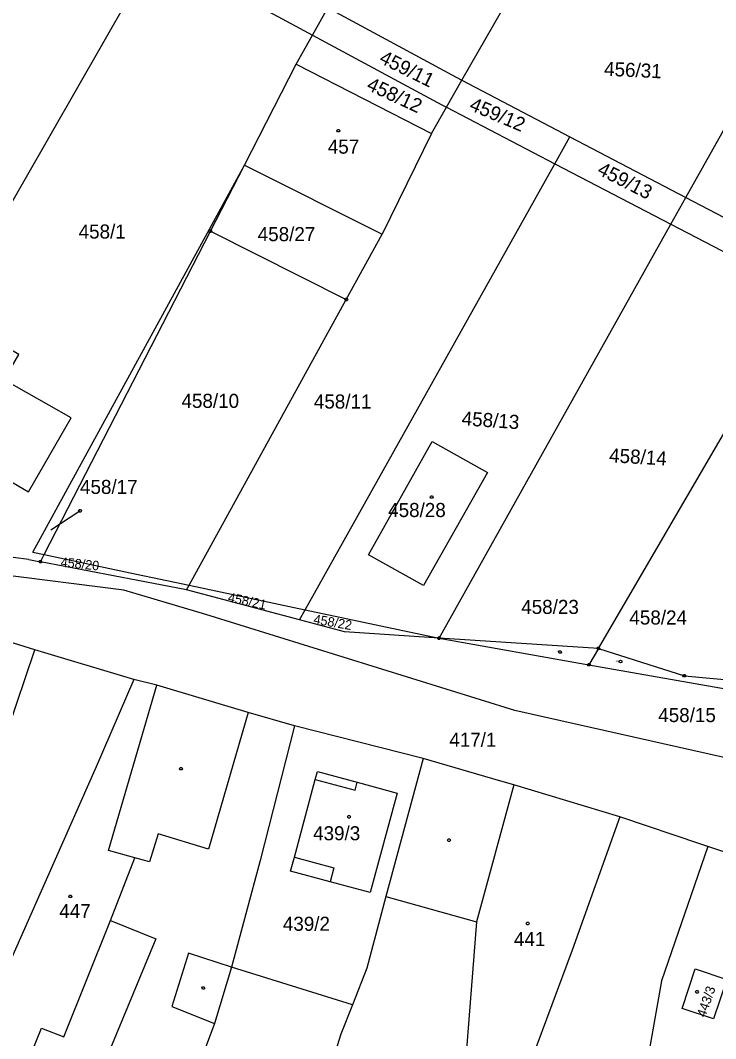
# Model space of a CAD drawing. Extents: x -634640 to -629202, y -1196156 to -1190068.
# Drawn here: x -631677.2 to -631593.2, y -1192457.5 to -1192334.4 of the extents above; entities that cross this region are included whole.
import ezdxf

# ---------------------------------------------------------------- set-up
doc = ezdxf.new("R2010")
doc.units = 0
for name, color, linetype in [('Vrstva 1', 7, 'Continuous'), ('Vrstva 2', 7, 'Continuous'), ('Vrstva 3', 7, 'Continuous'), ('Vrstva 4', 7, 'Continuous'), ('Vrstva 5', 7, 'Continuous'), ('Vrstva 7', 7, 'Continuous'), ('Vrstva 8', 7, 'Continuous')]:
    doc.layers.add(name, color=color, linetype=linetype)

msp = doc.modelspace()

# ---------------------------------------------------------------- linework, layer by layer
at = {"layer": 'Vrstva 1'}
for p, q in [((-631596.84, -1192355.81), (-631551.04, -1192273.99)), ((-631623.88, -1192341.65), (-631611.53, -1192319.92)), ((-631699.56, -1192393.62), (-631660.85, -1192325.98)), ((-631660.85, -1192325.98), (-631641.92, -1192336.19)), ((-631641.92, -1192336.19), (-631640.07, -1192332.88)), ((-631640.07, -1192332.88), (-631624.58, -1192341.28)), ((-631643.89, -1192339.71), (-631641.92, -1192336.19)), ((-631641.92, -1192336.19), (-631626.3, -1192344.61)), ((-631650.15, -1192351.9), (-631643.89, -1192339.71)), ((-631643.89, -1192339.71), (-631627.54, -1192348.09)), ((-631625.73, -1192344.91), (-631623.88, -1192341.65)), ((-631624.58, -1192341.28), (-631623.88, -1192341.65)), ((-631623.88, -1192341.65), (-631610.84, -1192348.48)), ((-631626.3, -1192344.61), (-631625.73, -1192344.91)), ((-631627.54, -1192348.09), (-631625.73, -1192344.91)), ((-631625.73, -1192344.91), (-631612.65, -1192351.73)), ((-631627.54, -1192348.09), (-631633.52, -1192360.26)), ((-631612.65, -1192351.73), (-631610.84, -1192348.48)), ((-631610.84, -1192348.48), (-631596.84, -1192355.81)), ((-631675.69, -1192398.68), (-631650.15, -1192351.9)), ((-631654.26, -1192359.89), (-631650.15, -1192351.9)), ((-631650.15, -1192351.9), (-631633.52, -1192360.26)), ((-631642.81, -1192405.64), (-631612.65, -1192351.73)), ((-631612.65, -1192351.73), (-631598.65, -1192359.03)), ((-631598.65, -1192359.03), (-631596.84, -1192355.81)), ((-631596.84, -1192355.81), (-631580.61, -1192364.32)), ((-631626.65, -1192409.06), (-631598.65, -1192359.03)), ((-631598.65, -1192359.03), (-631582.45, -1192367.48)), ((-631674.34, -1192398.96), (-631654.26, -1192359.89)), ((-631654.26, -1192359.89), (-631637.85, -1192368.14)), ((-631637.85, -1192368.14), (-631633.52, -1192360.26)), ((-631607.4, -1192410.3), (-631582.45, -1192367.48)), ((-631656.83, -1192402.67), (-631637.85, -1192368.14)), ((-631635.17, -1192398.98), (-631627.48, -1192385.29)), ((-631627.48, -1192385.29), (-631620.81, -1192389.06)), ((-631620.81, -1192389.06), (-631628.54, -1192402.72)), ((-631676.17, -1192399.56), (-631701.21, -1192396.5)), ((-631675.69, -1192398.68), (-631674.34, -1192398.96)), ((-631676.17, -1192399.56), (-631674.79, -1192399.83)), ((-631674.79, -1192399.83), (-631674.34, -1192398.96)), ((-631657.14, -1192403.23), (-631674.79, -1192399.83)), ((-631674.34, -1192398.96), (-631663.96, -1192401.16)), ((-631628.54, -1192402.72), (-631635.17, -1192398.98)), ((-631664.73, -1192403.25), (-631685.49, -1192400.66)), ((-631663.96, -1192401.16), (-631656.83, -1192402.67)), ((-631654.83, -1192406.19), (-631664.73, -1192403.25)), ((-631657.14, -1192403.23), (-631656.83, -1192402.67)), ((-631643.5, -1192406.87), (-631657.14, -1192403.23)), ((-631656.83, -1192402.67), (-631642.81, -1192405.64)), ((-631643.5, -1192406.87), (-631642.81, -1192405.64)), ((-631642.81, -1192405.64), (-631626.65, -1192409.06)), ((-631617.48, -1192417.8), (-631654.83, -1192406.19)), ((-631638.06, -1192408.32), (-631643.5, -1192406.87)), ((-631626.65, -1192409.06), (-631638.06, -1192408.32)), ((-631675.46, -1192410.46), (-631680.01, -1192409.08)), ((-631607.4, -1192410.3), (-631626.65, -1192409.06)), ((-631626.65, -1192409.06), (-631608.55, -1192412.27)), ((-631663.51, -1192414.07), (-631675.46, -1192410.46)), ((-631607.4, -1192410.3), (-631608.55, -1192412.27)), ((-631607.4, -1192410.3), (-631597.02, -1192413.6)), ((-631608.55, -1192412.27), (-631587.87, -1192415.94)), ((-631663.51, -1192414.07), (-631668.06, -1192424.6)), ((-631666.57, -1192434.71), (-631660.73, -1192414.76)), ((-631660.73, -1192414.76), (-631663.51, -1192414.07)), ((-631649.72, -1192418.05), (-631660.73, -1192414.76)), ((-631597.02, -1192413.6), (-631587.02, -1192414.54)), ((-631644.12, -1192419.68), (-631649.72, -1192418.05)), ((-631573.53, -1192427.73), (-631617.48, -1192417.8)), ((-631644.12, -1192419.68), (-631648.26, -1192435.93)), ((-631628.57, -1192423.59), (-631644.12, -1192419.68)), ((-631668.06, -1192424.6), (-631683.05, -1192458.47)), ((-631628.57, -1192423.59), (-631633.08, -1192440.27)), ((-631619.17, -1192426.33), (-631628.57, -1192423.59)), ((-631641.59, -1192426.15), (-631641.33, -1192425.18)), ((-631641.33, -1192425.18), (-631636.52, -1192426.47)), ((-631644.12, -1192435.54), (-631641.59, -1192426.15)), ((-631617.63, -1192426.79), (-631622.14, -1192443.33)), ((-631617.63, -1192426.79), (-631619.17, -1192426.33)), ((-631604.81, -1192430.67), (-631617.63, -1192426.79)), ((-631604.81, -1192430.67), (-631610.57, -1192446.78)), ((-631595.05, -1192433.96), (-631604.81, -1192430.67)), ((-631594.19, -1192434.24), (-631599.8, -1192450.48)), ((-631594.19, -1192434.24), (-631595.05, -1192433.96)), ((-631581.89, -1192438.36), (-631594.19, -1192434.24)), ((-631663.38, -1192435.6), (-631666.57, -1192434.71)), ((-631666.32, -1192443.2), (-631663.38, -1192435.6)), ((-631648.26, -1192435.93), (-631651.72, -1192448.81)), ((-631633.08, -1192440.27), (-631635.36, -1192448.94)), ((-631671.98, -1192457.26), (-631666.32, -1192443.2)), ((-631622.14, -1192443.33), (-631623.36, -1192459.26)), ((-631610.57, -1192446.78), (-631615.48, -1192459.99)), ((-631651.72, -1192448.81), (-631653.75, -1192455.62)), ((-631637.11, -1192453.38), (-631651.72, -1192448.81)), ((-631635.36, -1192448.94), (-631637.11, -1192453.38)), ((-631599.8, -1192450.48), (-631602.23, -1192464.48)), ((-631637.11, -1192453.38), (-631638.51, -1192456.92)), ((-631676.93, -1192461.8), (-631674.65, -1192456.19)), ((-631674.65, -1192456.19), (-631671.98, -1192457.26)), ((-631653.75, -1192455.62), (-631659.87, -1192471.73)), ((-631638.51, -1192456.92), (-631643.13, -1192471.72))]:
    msp.add_line(p, q, dxfattribs=at)
for points in [[(-631690.67, -1192385.37), (-631686.42, -1192387.83), (-631684.38, -1192386.65), (-631676.21, -1192391.4), (-631671.07, -1192382.44), (-631679.16, -1192377.83), (-631677.41, -1192374.77), (-631682.85, -1192371.59), (-631690.67, -1192385.37)], [(-631682.88, -1192418.91), (-631678.82, -1192420.38), (-631675.46, -1192410.46)], [(-631636.52, -1192426.47), (-631631.71, -1192427.8), (-631634.96, -1192439.8), (-631639.79, -1192438.5)], [(-631639.79, -1192438.5), (-631644.57, -1192437.22), (-631644.12, -1192435.54)], [(-631597.29, -1192453.81), (-631595.7, -1192449.03), (-631591.88, -1192450.3), (-631593.51, -1192455.07), (-631597.29, -1192453.81)]]:
    msp.add_lwpolyline(points, dxfattribs=at)
at = {"layer": 'Vrstva 3'}
for points in [[(-631671.09, -1192440.12), (-631671, -1192440.27), (-631671.09, -1192440.42), (-631671.27, -1192440.42), (-631671.36, -1192440.27), (-631671.27, -1192440.12), (-631671.09, -1192440.12)], [(-631615.85, -1192443.39), (-631615.76, -1192443.54), (-631615.85, -1192443.69), (-631616.03, -1192443.69), (-631616.12, -1192443.54), (-631616.03, -1192443.39), (-631615.85, -1192443.39)]]:
    msp.add_lwpolyline(points, dxfattribs=at)
at = {"layer": 'Vrstva 4'}
for p, q in [((-631649.72, -1192418.05), (-631654.5, -1192434.56)), ((-631660.57, -1192432.7), (-631661.61, -1192436.09)), ((-631654.5, -1192434.56), (-631660.57, -1192432.7)), ((-631661.61, -1192436.09), (-631663.38, -1192435.6)), ((-631633.08, -1192440.27), (-631622.14, -1192443.33)), ((-631666.32, -1192443.2), (-631660.86, -1192445.4)), ((-631660.86, -1192445.4), (-631668.2, -1192463.07)), ((-631656.9, -1192447.12), (-631658.9, -1192453.56)), ((-631651.72, -1192448.81), (-631656.9, -1192447.12)), ((-631658.9, -1192453.56), (-631653.75, -1192455.62))]:
    msp.add_line(p, q, dxfattribs=at)
for points in [[(-631641.59, -1192426.15), (-631636.78, -1192427.44), (-631636.52, -1192426.47)], [(-631644.12, -1192435.54), (-631639.34, -1192436.82), (-631639.79, -1192438.5)]]:
    msp.add_lwpolyline(points, dxfattribs=at)
at = {"layer": 'Vrstva 5'}
for points in [[(-631638.72, -1192347.6), (-631638.63, -1192347.75), (-631638.72, -1192347.9), (-631638.9, -1192347.9), (-631638.99, -1192347.75), (-631638.9, -1192347.6), (-631638.72, -1192347.6)], [(-631627.44, -1192391.86), (-631627.35, -1192392.01), (-631627.44, -1192392.16), (-631627.62, -1192392.16), (-631627.71, -1192392.01), (-631627.62, -1192391.86), (-631627.44, -1192391.86)], [(-631657.73, -1192424.69), (-631657.64, -1192424.84), (-631657.73, -1192424.99), (-631657.91, -1192424.99), (-631658, -1192424.84), (-631657.91, -1192424.69), (-631657.73, -1192424.69)], [(-631637.43, -1192430.5), (-631637.34, -1192430.65), (-631637.43, -1192430.8), (-631637.61, -1192430.8), (-631637.7, -1192430.65), (-631637.61, -1192430.5), (-631637.43, -1192430.5)], [(-631625.35, -1192433.33), (-631625.26, -1192433.48), (-631625.35, -1192433.63), (-631625.53, -1192433.63), (-631625.62, -1192433.48), (-631625.53, -1192433.33), (-631625.35, -1192433.33)], [(-631655.04, -1192451.19), (-631654.95, -1192451.34), (-631655.04, -1192451.49), (-631655.22, -1192451.49), (-631655.31, -1192451.34), (-631655.22, -1192451.19), (-631655.04, -1192451.19)], [(-631595.42, -1192451.66), (-631595.33, -1192451.81), (-631595.42, -1192451.96), (-631595.6, -1192451.96), (-631595.69, -1192451.81), (-631595.6, -1192451.66), (-631595.42, -1192451.66)]]:
    msp.add_lwpolyline(points, dxfattribs=at)
at = {"layer": 'Vrstva 7'}
msp.add_line((-631673.54, -1192395.97), (-631670.02, -1192393.68), dxfattribs=at)
for points in [[(-631669.845, -1192393.674), (-631669.922, -1192393.831), (-631670.097, -1192393.837), (-631670.195, -1192393.686), (-631670.118, -1192393.529), (-631669.943, -1192393.523), (-631669.845, -1192393.674)], [(-631611.944, -1192410.594), (-631611.86, -1192410.747), (-631611.956, -1192410.893), (-631612.136, -1192410.886), (-631612.22, -1192410.733), (-631612.124, -1192410.587), (-631611.944, -1192410.594)], [(-631604.571, -1192411.818), (-631604.582, -1192411.992), (-631604.741, -1192412.065), (-631604.889, -1192411.962), (-631604.878, -1192411.788), (-631604.719, -1192411.715), (-631604.571, -1192411.818)]]:
    msp.add_lwpolyline(points, dxfattribs=at)
at = {"layer": 'Vrstva 8'}
for points in [[(-631654.17, -1192359.74), (-631654.08, -1192359.89), (-631654.17, -1192360.04), (-631654.35, -1192360.04), (-631654.44, -1192359.89), (-631654.35, -1192359.74), (-631654.17, -1192359.74)], [(-631637.76, -1192367.99), (-631637.67, -1192368.14), (-631637.76, -1192368.29), (-631637.94, -1192368.29), (-631638.03, -1192368.14), (-631637.94, -1192367.99), (-631637.76, -1192367.99)], [(-631674.7, -1192399.68), (-631674.61, -1192399.83), (-631674.7, -1192399.98), (-631674.88, -1192399.98), (-631674.97, -1192399.83), (-631674.88, -1192399.68), (-631674.7, -1192399.68)], [(-631626.56, -1192408.91), (-631626.47, -1192409.06), (-631626.56, -1192409.21), (-631626.74, -1192409.21), (-631626.83, -1192409.06), (-631626.74, -1192408.91), (-631626.56, -1192408.91)], [(-631607.31, -1192410.15), (-631607.22, -1192410.3), (-631607.31, -1192410.45), (-631607.49, -1192410.45), (-631607.58, -1192410.3), (-631607.49, -1192410.15), (-631607.31, -1192410.15)], [(-631608.46, -1192412.12), (-631608.37, -1192412.27), (-631608.46, -1192412.42), (-631608.64, -1192412.42), (-631608.73, -1192412.27), (-631608.64, -1192412.12), (-631608.46, -1192412.12)], [(-631596.93, -1192413.45), (-631596.84, -1192413.6), (-631596.93, -1192413.75), (-631597.11, -1192413.75), (-631597.2, -1192413.6), (-631597.11, -1192413.45), (-631596.93, -1192413.45)]]:
    msp.add_lwpolyline(points, dxfattribs=at)

# ---------------------------------------------------------------- texts
at = {"layer": 'Vrstva 2'}
for s, height, rotation, p in [('459/11', 1.7, 333.46144, (-631633.998, -1192339.466)), ('456/31', 1.7, 357.29648, (-631606.743, -1192341.091)), ('458/12', 1.7, 335.06572, (-631635.515, -1192342.73)), ('459/12', 1.7, 336.95648, (-631623.102, -1192345.193)), ('459/13', 1.7, 332.94578, (-631607.659, -1192352.938)), ('458/13', 1.7, 356.03598, (-631623.953, -1192383.336)), ('458/14', 1.7, 356.60893, (-631606.143, -1192387.794)), ('458/20', 1.14, 354.25981, (-631672.387, -1192400.429)), ('458/21', 1.14, 348.07186, (-631652.217, -1192404.656)), ('458/22', 1.14, 350.2491, (-631641.871, -1192407.305)), ('443/3', 1.14, 70.70299, (-631594.494, -1192454.965))]:
    msp.add_text(s, height=height, rotation=rotation, dxfattribs=at).set_placement(p)
for s, height, p in [('457', 1.7, (-631640.083, -1192350.52)), ('458/1', 1.7, (-631670.173, -1192360.78)), ('458/27', 1.7, (-631648.545, -1192361.09)), ('458/10', 1.7, (-631657.753, -1192381.24)), ('458/11', 1.7, (-631641.763, -1192381.32)), ('458/28', 1.7, (-631632.789, -1192394.43)), ('458/17', 0.1, (-631673.801, -1192395.97)), ('458/23', 0.1, (-631612.619, -1192410.74)), ('458/24', 0.1, (-631605.313, -1192411.89)), ('458/15', 1.7, (-631600.173, -1192419.21)), ('439/3', 1.7, (-631641.858, -1192433.49)), ('447', 1.7, (-631672.513, -1192442.89)), ('439/2', 1.7, (-631645.508, -1192444.43)), ('441', 1.7, (-631617.603, -1192446.27))]:
    msp.add_text(s, height=height, dxfattribs=at).set_placement(p)
at = {"layer": 'Vrstva 7'}
for s, p in [('458/17', (-631670.007, -1192391.64)), ('458/23', (-631616.719, -1192406.14)), ('458/24', (-631603.659, -1192407.42)), ('417/1', (-631625.409, -1192422.19))]:
    msp.add_text(s, height=1.7, dxfattribs=at).set_placement(p)

doc.saveas('drawing.dxf')
